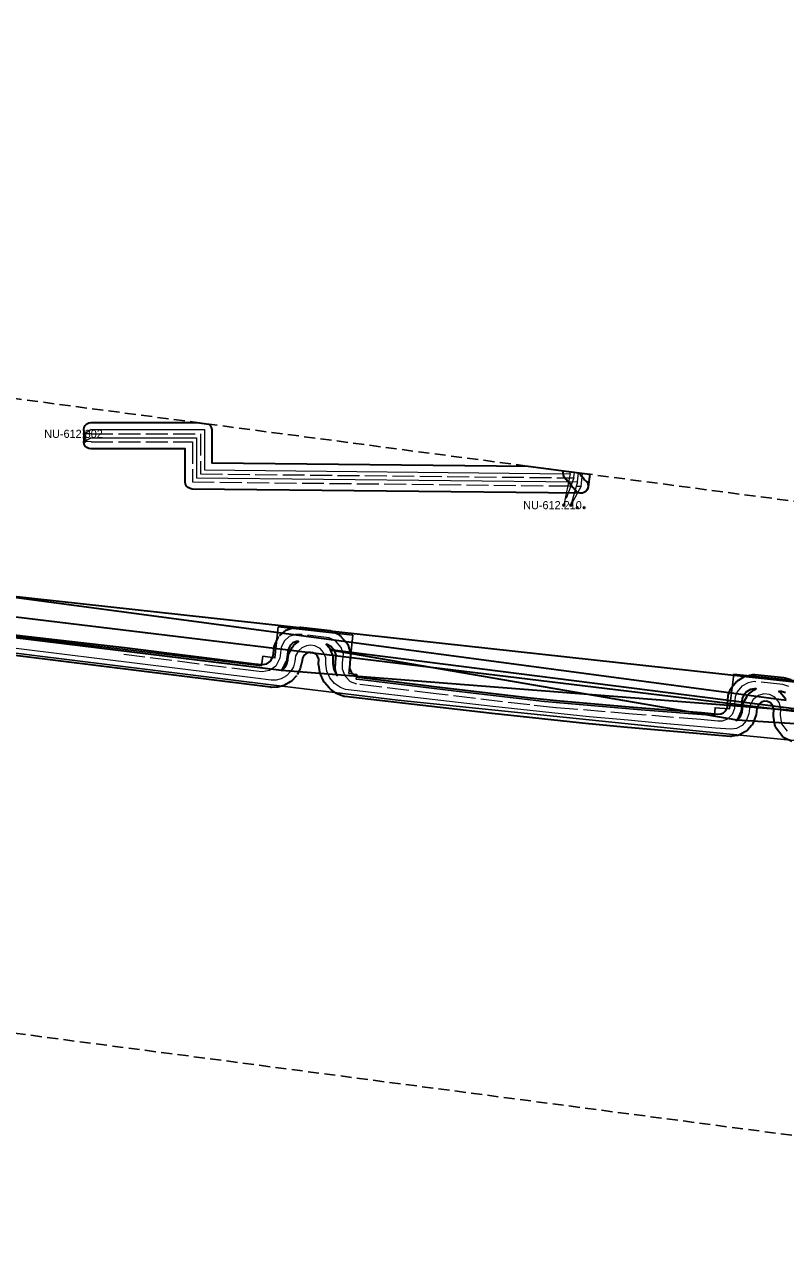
# Model space of a CAD drawing. Extents: x -451331 to -449998, y -1101254 to -1101132.
# Drawn here: x -450624 to -450549.1, y -1101253.5 to -1101132.1 of the extents above; entities that cross this region are included whole.
import ezdxf

# ---------------------------------------------------------------- set-up
doc = ezdxf.new("R2010")
doc.units = 0
doc.header["$LTSCALE"] = 0.36
doc.header["$PDMODE"] = 32
doc.header["$PDSIZE"] = 0.18
doc.linetypes.add('LONG_DASHED', pattern=[7.5, 6, -1.5])
doc.linetypes.add('MEDIUM_DASHED', pattern=[4.5, 3, -1.5])
for name, color, linetype, lineweight in [('2', 7, 'Continuous', 13), ('3', 7, 'Continuous', 25), ('62', 7, 'MEDIUM_DASHED', 25), ('8', 7, 'Continuous', 35)]:
    doc.layers.add(name, color=color, linetype=linetype, lineweight=lineweight)
doc.layers.add('4', color=7, linetype='Continuous')
doc.layers.add('7', color=7, linetype='Continuous')

msp = doc.modelspace()

# ---------------------------------------------------------------- linework, layer by layer
at = {"layer": '2'}
for p, q in [((-450617.478, -1101171.989), (-450618.087, -1101172.398)), ((-450617.478, -1101172.789), (-450618.086, -1101173.14)), ((-450570.27, -1101176.333), (-450570.244, -1101176.138)), ((-450569.568, -1101177.14), (-450569.452, -1101176.243)), ((-450570.27, -1101176.333), (-450570.912, -1101179.425)), ((-450569.568, -1101177.14), (-450570.233, -1101179.425))]:
    msp.add_line(p, q, dxfattribs=at)
at = {"layer": '2', "linetype": 'LONG_DASHED'}
for p, q in [((-450617.478, -1101172.388), (-450618.087, -1101172.398)), ((-450617.478, -1101173.188), (-450618.086, -1101173.14)), ((-450569.917, -1101176.736), (-450569.847, -1101176.19)), ((-450569.917, -1101176.736), (-450570.912, -1101179.425)), ((-450569.215, -1101177.545), (-450569.054, -1101176.295)), ((-450569.215, -1101177.545), (-450570.233, -1101179.425))]:
    msp.add_line(p, q, dxfattribs=at)
at = {"layer": '2'}
for points in [[(-450617.478, -1101171.989), (-450606.295, -1101171.989), (-450606.295, -1101175.949), (-450570.27, -1101176.333)], [(-450617.478, -1101172.789), (-450607.094, -1101172.789), (-450607.094, -1101176.741), (-450569.568, -1101177.14)], [(-450548.883, -1101201.702), (-450549.441, -1101200.956), (-450549.571, -1101200.109), (-450549.524, -1101199.5), (-450549.694, -1101198.855), (-450550.121, -1101198.339), (-450550.648, -1101198.071), (-450551.204, -1101198.018), (-450551.74, -1101198.181), (-450552.246, -1101198.572), (-450552.587, -1101199.191), (-450552.674, -1101199.992), (-450552.94, -1101200.673), (-450553.341, -1101201.112), (-450553.889, -1101201.409), (-450554.459, -1101201.504), (-450555.97, -1101201.377), (-450557.766, -1101201.219), (-450561.906, -1101200.854), (-450564.562, -1101200.619), (-450568.4, -1101200.274), (-450577.893, -1101199.265), (-450592.406, -1101197.583), (-450592.899, -1101197.392), (-450593.498, -1101196.976), (-450593.942, -1101196.446), (-450594.246, -1101195.779), (-450594.357, -1101195.084), (-450594.353, -1101194.454), (-450594.568, -1101193.926), (-450594.914, -1101193.547), (-450595.431, -1101193.281), (-450595.871, -1101193.219), (-450596.264, -1101193.271), (-450596.701, -1101193.465), (-450597.056, -1101193.78), (-450597.325, -1101194.263), (-450597.416, -1101194.812), (-450597.548, -1101195.337), (-450597.79, -1101195.786), (-450598.216, -1101196.232), (-450598.754, -1101196.537), (-450599.24, -1101196.662), (-450599.727, -1101196.67), (-450601.284, -1101196.474), (-450635.748, -1101192.194)]]:
    msp.add_lwpolyline(points, dxfattribs=at)
at = {"layer": '2', "linetype": 'LONG_DASHED'}
for points in [[(-450617.478, -1101172.388), (-450606.695, -1101172.388), (-450606.695, -1101176.344), (-450569.917, -1101176.736)], [(-450617.478, -1101173.188), (-450607.494, -1101173.188), (-450607.494, -1101177.136), (-450569.215, -1101177.545)], [(-450548.75, -1101197.278), (-450549.325, -1101197.105), (-450552.159, -1101196.8), (-450552.754, -1101196.912), (-450553.364, -1101197.257), (-450553.829, -1101197.811), (-450554.032, -1101198.318), (-450554.1, -1101199.059), (-450554.105, -1101199.45), (-450554.344, -1101200.061), (-450554.789, -1101200.489), (-450555.306, -1101200.687), (-450555.751, -1101200.698), (-450557.411, -1101200.548), (-450564.138, -1101200.005), (-450571.689, -1101199.373), (-450574.259, -1101199.106), (-450583.487, -1101198.002), (-450591.281, -1101197.058), (-450591.915, -1101196.817), (-450592.46, -1101196.279), (-450592.717, -1101195.593), (-450592.696, -1101194.952), (-450592.623, -1101194.116), (-450592.826, -1101193.445), (-450593.411, -1101192.796), (-450594.01, -1101192.48), (-450596.89, -1101192.149), (-450597.377, -1101192.159), (-450597.961, -1101192.373), (-450598.45, -1101192.815), (-450598.74, -1101193.457), (-450598.869, -1101194.501), (-450599.262, -1101195.27), (-450599.89, -1101195.715), (-450600.608, -1101195.842), (-450601.474, -1101195.739), (-450614.251, -1101194.149)]]:
    msp.add_lwpolyline(points, dxfattribs=at)
at = {"layer": '3'}
for points in [[(-450456.247, -1101207.547), (-450467.469, -1101207.201), (-450502.327, -1101205.863), (-450513.036, -1101205.268), (-450527.393, -1101204.583), (-450541.226, -1101203.307), (-450557.885, -1101201.66), (-450587.245, -1101198.634), (-450599.721, -1101197.12), (-450623.306, -1101194.193), (-450636.866, -1101192.511), (-450644.042, -1101191.642), (-450670.806, -1101187.894), (-450716.119, -1101180.809), (-450724.513, -1101179.55), (-450750.507, -1101175.197)], [(-450633.749, -1101191.298), (-450612.722, -1101193.79), (-450600.689, -1101195.243), (-450600.562, -1101194.314), (-450599.361, -1101194.474), (-450599.038, -1101191.417), (-450591.696, -1101192.218), (-450592.083, -1101196.003), (-450591.307, -1101196.1), (-450591.355, -1101196.548), (-450590.707, -1101196.632), (-450581.504, -1101197.731), (-450572.828, -1101198.755), (-450563.303, -1101199.576), (-450556.064, -1101200.152), (-450556.062, -1101200.069), (-450556.009, -1101199.381), (-450554.603, -1101199.489), (-450554.157, -1101196.058), (-450547.172, -1101196.789)]]:
    msp.add_lwpolyline(points, dxfattribs=at)
at = {"layer": '4'}
for p in [(-450618.087, -1101172.398), (-450618.086, -1101173.139), (-450570.912, -1101179.424), (-450570.233, -1101179.424)]:
    msp.add_point(p, dxfattribs=at)
at = {"layer": '62'}
msp.add_lwpolyline([(-450786.261, -1101210.25), (-451322.174, -1101190.711), (-451330.547, -1101132.096), (-450766.722, -1101150.239), (-450459.689, -1101190.711), (-449997.743, -1101194.898), (-449997.743, -1101249.327), (-450456.897, -1101253.514)], close=True, dxfattribs=at)
at = {"layer": '7'}
for p in [(-450618.087, -1101172.398), (-450618.086, -1101172.645), (-450618.086, -1101172.892), (-450618.086, -1101173.139), (-450570.912, -1101179.424), (-450570.233, -1101179.424), (-450569.587, -1101179.67), (-450568.908, -1101179.67)]:
    msp.add_point(p, dxfattribs=at)
at = {"layer": '8'}
for points in [[(-450569.25, -1101176.526), (-450569.15, -1101176.579), (-450568.997, -1101176.735), (-450568.901, -1101176.929), (-450568.798, -1101176.983), (-450568.645, -1101177.139), (-450568.548, -1101177.335), (-450568.516, -1101177.552), (-450568.552, -1101177.768), (-450568.654, -1101177.962), (-450568.81, -1101178.115), (-450569.006, -1101178.212), (-450569.223, -1101178.245), (-450607.502, -1101177.837), (-450607.717, -1101177.8), (-450607.91, -1101177.7), (-450608.063, -1101177.546), (-450608.161, -1101177.351), (-450608.195, -1101177.136), (-450608.195, -1101173.888), (-450617.478, -1101173.888), (-450617.694, -1101173.854), (-450617.889, -1101173.755), (-450618.044, -1101173.6), (-450618.143, -1101173.405), (-450618.178, -1101173.188), (-450618.146, -1101172.989), (-450618.178, -1101172.789), (-450618.146, -1101172.589), (-450618.178, -1101172.388), (-450618.146, -1101172.188), (-450618.178, -1101171.989), (-450618.143, -1101171.772), (-450618.044, -1101171.577), (-450617.889, -1101171.422), (-450617.694, -1101171.323), (-450617.478, -1101171.289), (-450607.034, -1101171.289), (-450605.862, -1101171.443), (-450605.728, -1101171.577), (-450605.629, -1101171.772), (-450605.594, -1101171.989), (-450605.594, -1101175.256), (-450574.416, -1101175.588), (-450569.431, -1101176.245), (-450569.347, -1101176.331)], [(-450569.868, -1101177.772), (-450570.048, -1101177.649), (-450570.182, -1101177.476), (-450570.221, -1101177.367), (-450570.398, -1101177.245), (-450570.532, -1101177.072), (-450570.57, -1101176.964), (-450570.75, -1101176.842), (-450570.884, -1101176.668), (-450570.957, -1101176.462), (-450570.964, -1101176.243), (-450570.938, -1101176.047), (-450568.36, -1101176.386), (-450568.521, -1101177.634), (-450568.583, -1101177.844), (-450568.707, -1101178.025), (-450568.88, -1101178.159), (-450569.086, -1101178.232), (-450569.305, -1101178.239), (-450569.515, -1101178.177), (-450569.696, -1101178.054), (-450569.83, -1101177.88)]]:
    msp.add_lwpolyline(points, close=True, dxfattribs=at)
for points in [[(-450549.017, -1101198.677), (-450719.127, -1101175.983)], [(-450726.33, -1101177.289), (-450505.347, -1101201.513)], [(-450724.607, -1101178.355), (-450510.557, -1101204.272), (-450510.479, -1101204.276), (-450510.191, -1101204.202)], [(-450465.384, -1101206.14), (-450598.72, -1101195.713), (-450598.651, -1101195.674), (-450598.362, -1101195.37), (-450598.206, -1101195.081), (-450598.102, -1101194.669), (-450598.015, -1101194.148), (-450597.985, -1101194.032), (-450597.936, -1101193.922), (-450597.667, -1101193.439), (-450597.601, -1101193.342), (-450597.521, -1101193.258), (-450597.167, -1101192.942), (-450597.106, -1101192.894), (-450597.04, -1101192.853), (-450597.246, -1101192.856), (-450597.592, -1101192.983), (-450597.872, -1101193.237), (-450598.059, -1101193.649), (-450598.175, -1101194.587), (-450598.2, -1101194.706), (-450598.246, -1101194.819), (-450598.638, -1101195.588), (-450598.676, -1101195.653), (-450598.72, -1101195.713), (-450643.227, -1101190.26)], [(-450598.919, -1101192.296), (-450598.43, -1101191.854), (-450598.36, -1101191.798), (-450598.284, -1101191.752), (-450598.201, -1101191.715), (-450597.616, -1101191.501), (-450597.506, -1101191.471), (-450597.393, -1101191.459), (-450596.903, -1101191.45), (-450596.834, -1101191.452), (-450596.81, -1101191.454), (-450593.93, -1101191.785), (-450593.845, -1101191.8), (-450593.762, -1101191.825), (-450593.684, -1101191.861), (-450593.085, -1101192.176), (-450593.015, -1101192.219), (-450592.95, -1101192.269), (-450592.891, -1101192.327), (-450592.306, -1101192.976), (-450592.243, -1101193.057), (-450592.193, -1101193.147), (-450592.156, -1101193.242), (-450591.953, -1101193.914), (-450591.932, -1101194), (-450591.923, -1101194.089), (-450591.925, -1101194.178), (-450591.997, -1101194.994), (-450592.013, -1101195.477), (-450591.858, -1101195.889), (-450591.528, -1101196.215), (-450591.113, -1101196.373), (-450583.404, -1101197.307), (-450574.181, -1101198.41), (-450571.623, -1101198.676), (-450564.081, -1101199.307), (-450557.354, -1101199.85), (-450557.348, -1101199.851), (-450555.728, -1101199.998), (-450555.444, -1101199.99), (-450555.172, -1101199.886), (-450554.94, -1101199.663), (-450554.803, -1101199.313), (-450554.799, -1101199.049), (-450554.799, -1101199.022), (-450554.797, -1101198.996), (-450554.729, -1101198.254), (-450554.713, -1101198.156), (-450554.683, -1101198.06), (-450554.479, -1101197.551), (-450554.43, -1101197.453), (-450554.367, -1101197.363), (-450553.899, -1101196.807), (-450553.842, -1101196.746), (-450553.778, -1101196.693), (-450553.708, -1101196.648), (-450553.099, -1101196.303), (-450552.995, -1101196.255), (-450552.885, -1101196.225), (-450552.29, -1101196.112), (-450552.188, -1101196.1), (-450552.085, -1101196.103), (-450549.25, -1101196.409), (-450549.196, -1101196.417), (-450549.123, -1101196.435), (-450548.548, -1101196.608)], [(-450597.224, -1101196.197), (-450597.284, -1101196.269), (-450597.709, -1101196.715), (-450597.785, -1101196.784), (-450597.87, -1101196.84), (-450598.408, -1101197.146), (-450598.492, -1101197.186), (-450598.58, -1101197.215), (-450599.065, -1101197.34), (-450599.146, -1101197.356), (-450599.228, -1101197.362), (-450599.715, -1101197.37), (-450599.746, -1101197.37), (-450599.815, -1101197.365), (-450601.371, -1101197.169), (-450635.833, -1101192.888)], [(-450625.946, -1101192.093), (-450614.171, -1101193.454), (-450614.165, -1101193.455), (-450601.39, -1101195.045), (-450600.628, -1101195.135), (-450600.166, -1101195.053), (-450599.807, -1101194.799), (-450599.549, -1101194.293), (-450599.435, -1101193.371), (-450599.414, -1101193.267), (-450599.378, -1101193.168), (-450599.087, -1101192.526), (-450599.042, -1101192.442), (-450598.986, -1101192.365)], [(-450510.557, -1101204.272), (-450593.919, -1101193.663), (-450593.705, -1101194.19), (-450593.676, -1101194.276), (-450593.659, -1101194.365), (-450593.653, -1101194.455), (-450593.656, -1101195.03), (-450593.57, -1101195.575), (-450593.344, -1101196.07), (-450593.239, -1101196.195), (-450593.373, -1101195.839), (-450593.399, -1101195.751), (-450593.414, -1101195.661), (-450593.417, -1101195.569), (-450593.395, -1101194.928), (-450593.395, -1101194.915), (-450593.393, -1101194.891), (-450593.332, -1101194.19), (-450593.45, -1101193.798), (-450593.848, -1101193.357), (-450594.22, -1101193.16), (-450594.33, -1101193.148), (-450594.05, -1101193.455), (-450593.999, -1101193.519), (-450593.955, -1101193.588), (-450593.919, -1101193.663), (-450553.859, -1101200.567), (-450553.932, -1101200.637), (-450553.778, -1101200.553), (-450553.545, -1101200.297), (-450553.36, -1101199.824), (-450553.283, -1101199.116), (-450553.267, -1101199.025), (-450553.24, -1101198.937), (-450553.201, -1101198.854), (-450552.859, -1101198.234), (-450552.808, -1101198.155), (-450552.747, -1101198.083), (-450552.676, -1101198.02), (-450552.168, -1101197.627), (-450552.078, -1101197.568), (-450551.98, -1101197.523), (-450552.131, -1101197.507), (-450552.51, -1101197.579), (-450552.909, -1101197.804), (-450553.221, -1101198.176), (-450553.344, -1101198.483), (-450553.4, -1101199.096), (-450553.405, -1101199.46), (-450553.412, -1101199.543), (-450553.428, -1101199.625), (-450553.453, -1101199.704), (-450553.691, -1101200.316), (-450553.735, -1101200.407), (-450553.791, -1101200.491), (-450553.859, -1101200.567), (-450465.384, -1101206.14)], [(-450548.459, -1101202.693), (-450549.193, -1101202.329), (-450549.287, -1101202.274), (-450549.371, -1101202.204), (-450549.443, -1101202.121), (-450550.002, -1101201.375), (-450550.062, -1101201.279), (-450550.106, -1101201.174), (-450550.133, -1101201.064), (-450550.263, -1101200.214), (-450550.27, -1101200.135), (-450550.269, -1101200.055), (-450550.231, -1101199.564), (-450550.332, -1101199.182), (-450550.568, -1101198.897), (-450550.846, -1101198.755), (-450551.133, -1101198.728), (-450551.414, -1101198.813), (-450551.703, -1101199.037), (-450551.907, -1101199.406), (-450551.978, -1101200.068), (-450551.994, -1101200.159), (-450552.022, -1101200.247), (-450552.289, -1101200.928), (-450552.325, -1101201.005), (-450552.369, -1101201.078), (-450552.423, -1101201.144), (-450552.825, -1101201.585), (-450552.91, -1101201.664), (-450553.007, -1101201.728), (-450553.555, -1101202.025), (-450553.661, -1101202.071), (-450553.773, -1101202.1), (-450554.344, -1101202.195), (-450554.431, -1101202.204), (-450554.518, -1101202.202), (-450556.03, -1101202.075), (-450557.828, -1101201.916), (-450561.968, -1101201.551), (-450564.624, -1101201.317), (-450568.462, -1101200.972), (-450568.474, -1101200.971), (-450577.967, -1101199.961), (-450577.973, -1101199.96), (-450592.486, -1101198.278), (-450592.574, -1101198.263), (-450592.659, -1101198.236), (-450593.152, -1101198.045), (-450593.228, -1101198.01), (-450593.299, -1101197.967), (-450593.897, -1101197.552), (-450593.97, -1101197.493), (-450594.035, -1101197.425), (-450594.479, -1101196.894), (-450594.534, -1101196.819), (-450594.578, -1101196.737), (-450594.883, -1101196.07), (-450594.916, -1101195.982), (-450594.937, -1101195.89), (-450595.048, -1101195.193), (-450595.056, -1101195.121), (-450595.056, -1101195.08), (-450595.054, -1101194.589), (-450595.169, -1101194.306), (-450595.346, -1101194.112), (-450595.646, -1101193.958), (-450595.874, -1101193.925), (-450596.072, -1101193.952), (-450596.318, -1101194.061), (-450596.502, -1101194.225), (-450596.654, -1101194.498), (-450596.726, -1101194.927), (-450596.732, -1101194.96), (-450596.737, -1101194.983), (-450596.869, -1101195.508), (-450596.896, -1101195.591), (-450596.932, -1101195.67), (-450597.174, -1101196.118)], [(-450549.07, -1101197.913), (-450549.465, -1101197.794), (-450549.718, -1101197.767), (-450549.646, -1101197.825), (-450549.582, -1101197.892), (-450549.155, -1101198.409), (-450549.096, -1101198.491), (-450549.05, -1101198.581)]]:
    msp.add_lwpolyline(points, dxfattribs=at)

# ---------------------------------------------------------------- texts
at = {"layer": '4'}
for s, p in [('NU-612.302', (-450622.087, -1101172.798)), ('NU-612.210', (-450574.912, -1101179.824))]:
    msp.add_text(s, height=0.8, dxfattribs=at).set_placement(p)

doc.saveas('drawing.dxf')
